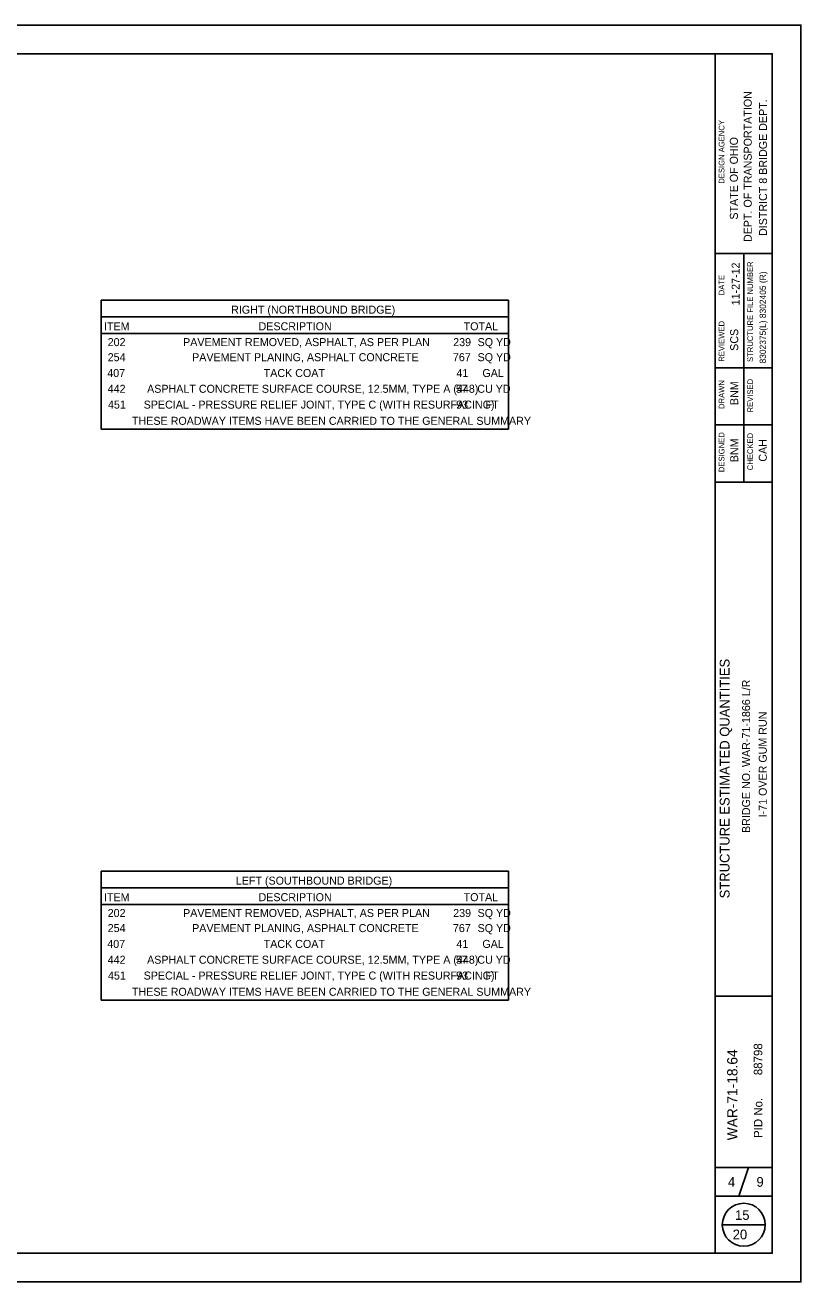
# Model space of a CAD drawing. Extents: x -17.7 to 16.3, y -7.1 to 14.9.
# Drawn here: x 2.71 to 16.28, y -7.05 to 14.95 of the extents above; entities that cross this region are included whole.
import ezdxf

# ---------------------------------------------------------------- set-up
doc = ezdxf.new("R2010")
doc.units = 0
for name, color, linetype in [('SH_Border', 7, 'Continuous'), ('SH_Cut_Line', 7, 'Continuous'), ('SH_Data', 7, 'Continuous'), ('SH_Text', 7, 'Continuous')]:
    doc.layers.add(name, color=color, linetype=linetype)

msp = doc.modelspace()

# ---------------------------------------------------------------- linework, layer by layer
at = {"layer": 'SH_Border'}
for p, q in [((14.785, -6.554), (14.785, 14.446)), ((14.785, 10.946), (15.785, 10.946)), ((15.285, 6.946), (15.285, 10.946)), ((14.785, 8.946), (15.785, 8.946)), ((14.785, 7.946), (15.785, 7.946)), ((14.785, 6.946), (15.785, 6.946)), ((14.785, -2.054), (15.785, -2.054)), ((14.785, -5.054), (15.785, -5.054)), ((15.201, -5.554), (15.368, -5.054)), ((14.785, -5.554), (15.785, -5.554))]:
    msp.add_line(p, q, dxfattribs=at)
msp.add_lwpolyline([(-15.715, 14.446), (15.785, 14.446), (15.785, -6.554), (-15.715, -6.554)], close=True, dxfattribs=at)
at = {"layer": 'SH_Cut_Line'}
msp.add_lwpolyline([(-17.715, -7.054), (16.285, -7.054), (16.285, 14.946), (-17.715, 14.946)], close=True, dxfattribs=at)
at = {"layer": 'SH_Data'}
msp.add_line((14.91, -6.054), (15.66, -6.054), dxfattribs=at)
msp.add_circle((15.285, -6.054), 0.375, dxfattribs=at)
at = {"layer": 'SH_Text'}
for p, q in [((4.035, 10.13), (11.165, 10.13)), ((4.035, 10.13), (4.035, 7.874)), ((11.165, 10.13), (11.165, 7.874)), ((4.035, 9.839), (11.165, 9.839)), ((4.035, 9.549), (11.165, 9.549)), ((4.035, 7.874), (11.165, 7.874)), ((4.035, 0.136), (11.165, 0.136)), ((4.035, 0.136), (4.035, -2.121)), ((11.165, 0.136), (11.165, -2.121)), ((4.035, -0.155), (11.165, -0.155)), ((4.035, -0.446), (11.165, -0.446)), ((4.035, -2.121), (11.165, -2.121))]:
    msp.add_line(p, q, dxfattribs=at)

# ---------------------------------------------------------------- texts
at = {"layer": 'SH_Data'}
for s, height, p in [('   DEPT. OF TRANSPORTATION   ', 0.14, (15.425, 10.993)), ('   DISTRICT 8 BRIDGE DEPT.   ', 0.14, (15.692, 11.099)), ('DESIGN AGENCY', 0.1, (14.947, 12.17)), ('        STATE OF OHIO        ', 0.14, (15.182, 11.125)), ('11-27-12', 0.14, (15.214, 10.041)), ('STRUCTURE FILE NUMBER', 0.1, (15.447, 9.049)), ('DATE', 0.1, (14.947, 10.217)), ('8302375(L) 8302405 (R)', 0.11, (15.673, 9.023)), ('REVIEWED', 0.1, (14.947, 9.054)), ('SCS', 0.14, (15.188, 9.244)), ('DRAWN', 0.1, (14.947, 8.227)), ('BNM', 0.14, (15.188, 8.295)), ('REVISED', 0.1, (15.447, 8.166)), ('DESIGNED', 0.1, (14.947, 7.121)), ('CHECKED', 0.1, (15.447, 7.154)), ('BNM', 0.14, (15.188, 7.295)), ('CAH', 0.14, (15.688, 7.304)), ('STRUCTURE ESTIMATED QUANTITIES', 0.17, (15.036, -0.34)), ('   BRIDGE NO. WAR-71-1866 L/R   ', 0.14, (15.396, 0.648)), ('       I-71 OVER GUM RUN        ', 0.14, (15.688, 0.714)), ('WAR-71-18.64', 0.18, (15.175, -4.576)), ('88798 ', 0.15, (15.61, -3.436)), ('PID No.', 0.15, (15.612, -4.535))]:
    msp.add_text(s, height=height, rotation=90, dxfattribs=at).set_placement(p)
for s, p in [('4', (15.009, -5.389)), ('9', (15.508, -5.389)), (' 15 ', (15.07, -5.969)), (' 20 ', (15.029, -6.309))]:
    msp.add_text(s, height=0.17, dxfattribs=at).set_placement(p)
at = {"layer": 'SH_Text'}
for s, p in [('RIGHT (NORTHBOUND BRIDGE)', (6.312, 9.895)), ('ITEM', (4.087, 9.604)), ('DESCRIPTION', (6.792, 9.604)), ('TOTAL', (10.382, 9.604)), ('202', (4.151, 9.327)), ('PAVEMENT REMOVED, ASPHALT, AS PER PLAN', (5.471, 9.327)), ('239', (10.199, 9.327)), ('SQ YD', (10.626, 9.327)), ('254', (4.151, 9.063)), ('PAVEMENT PLANING, ASPHALT CONCRETE', (5.629, 9.063)), ('767', (10.194, 9.063)), ('SQ YD', (10.626, 9.063)), ('407', (4.144, 8.786)), ('TACK COAT', (6.882, 8.786)), ('41', (10.256, 8.786)), ('GAL', (10.71, 8.786)), ('442', (4.151, 8.51)), ('ASPHALT CONCRETE SURFACE COURSE, 12.5MM, TYPE A (448)', (4.841, 8.51)), ('57', (10.245, 8.51)), ('CU YD', (10.621, 8.51)), ('451', (4.156, 8.233)), ('SPECIAL - PRESSURE RELIEF JOINT, TYPE C (WITH RESURFACING)', (4.781, 8.233)), ('93', (10.251, 8.233)), ('FT', (10.766, 8.233)), ('THESE ROADWAY ITEMS HAVE BEEN CARRIED TO THE GENERAL SUMMARY', (4.577, 7.949)), ('LEFT (SOUTHBOUND BRIDGE)', (6.394, -0.1)), ('ITEM', (4.087, -0.39)), ('DESCRIPTION', (6.792, -0.39)), ('TOTAL', (10.382, -0.39)), ('202', (4.151, -0.667)), ('PAVEMENT REMOVED, ASPHALT, AS PER PLAN', (5.471, -0.667)), ('239', (10.199, -0.667)), ('SQ YD', (10.626, -0.667)), ('254', (4.151, -0.931)), ('PAVEMENT PLANING, ASPHALT CONCRETE', (5.629, -0.931)), ('767', (10.194, -0.931)), ('SQ YD', (10.626, -0.931)), ('407', (4.144, -1.208)), ('TACK COAT', (6.882, -1.208)), ('41', (10.256, -1.208)), ('GAL', (10.71, -1.208)), ('442', (4.151, -1.485)), ('ASPHALT CONCRETE SURFACE COURSE, 12.5MM, TYPE A (448)', (4.841, -1.485)), ('57', (10.245, -1.485)), ('CU YD', (10.621, -1.485)), ('451', (4.156, -1.762)), ('SPECIAL - PRESSURE RELIEF JOINT, TYPE C (WITH RESURFACING)', (4.781, -1.762)), ('93', (10.251, -1.762)), ('FT', (10.766, -1.762)), ('THESE ROADWAY ITEMS HAVE BEEN CARRIED TO THE GENERAL SUMMARY', (4.577, -2.046))]:
    msp.add_text(s, height=0.1401, dxfattribs=at).set_placement(p)

doc.saveas('drawing.dxf')
